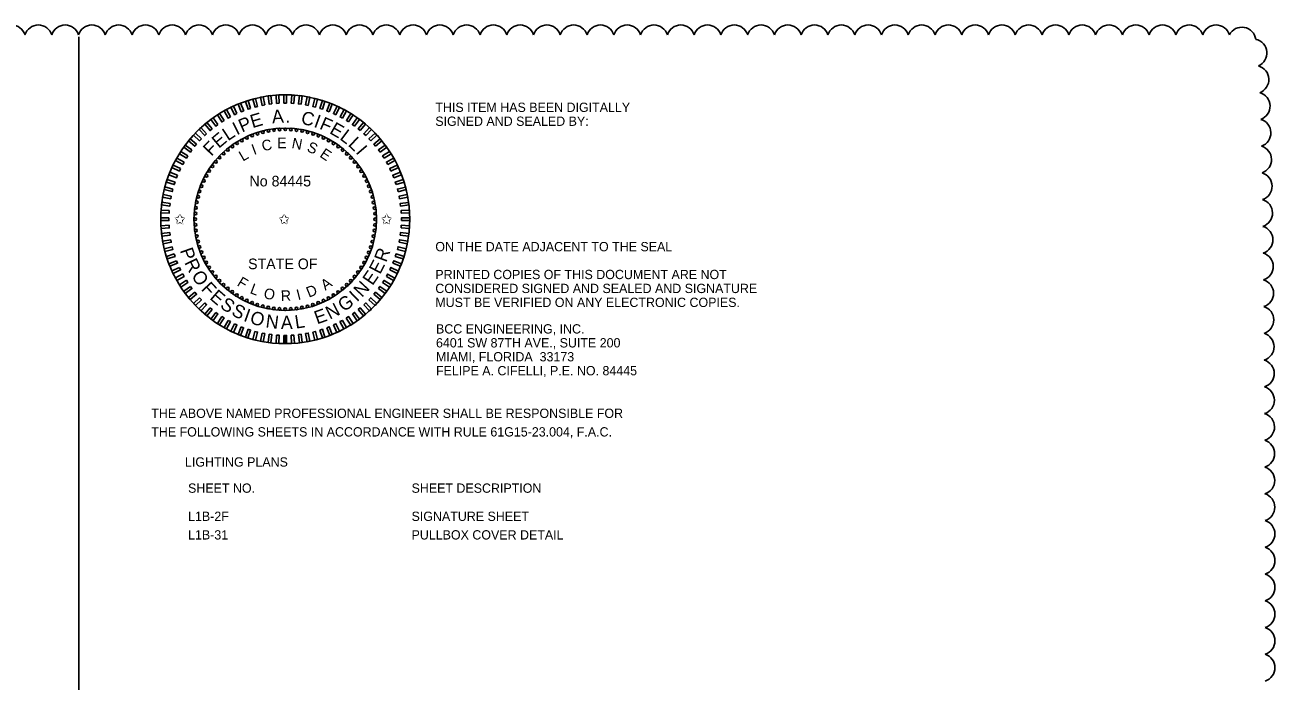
# Model space of a CAD drawing. Extents: x -811.2 to -767.6, y -2295.2 to -2235.1.
# Drawn here: x -777.02 to -767.6, y -2264.84 to -2259.9 of the extents above; entities that cross this region are included whole.
import ezdxf

# ---------------------------------------------------------------- set-up
doc = ezdxf.new("R2010")
doc.units = 0
for name, color, linetype in [('Cloud_dp', 7, 'Continuous'), ('PlotBorder_dp', 7, 'Continuous'), ('TextMinor', 7, 'Continuous'), ('TextMisc', 7, 'Continuous'), ('TextNotes', 7, 'Continuous'), ('TextShtNo', 7, 'Continuous')]:
    doc.layers.add(name, color=color, linetype=linetype)

msp = doc.modelspace()

# ---------------------------------------------------------------- linework, layer by layer
at = {"layer": 'Cloud_dp'}
for centre, radius, start, end in [((-777.1178, -2260.0023), 0.1057, 17.52079, 162.52079), ((-776.9163, -2260.0022), 0.1057, 17.51719, 162.51719), ((-776.7147, -2260.0022), 0.1057, 17.51375, 162.51375), ((-776.5132, -2260.0021), 0.1057, 17.51046, 162.51046), ((-776.3116, -2260.0021), 0.1057, 17.50731, 162.50731), ((-776.1101, -2260.0021), 0.1057, 17.50428, 162.50428), ((-775.9085, -2260.0021), 0.1057, 17.50138, 162.50138), ((-775.707, -2260.0021), 0.1057, 17.5, 162.5), ((-775.5054, -2260.0021), 0.1057, 17.5, 162.5), ((-775.3039, -2260.0021), 0.1057, 17.5, 162.5), ((-775.1023, -2260.0021), 0.1057, 17.5, 162.5), ((-774.9008, -2260.0021), 0.1057, 17.5, 162.5), ((-774.6992, -2260.0021), 0.1057, 17.5, 162.5), ((-774.4977, -2260.0021), 0.1057, 17.5, 162.5), ((-774.2961, -2260.0021), 0.1057, 17.5, 162.5), ((-774.0946, -2260.0021), 0.1057, 17.5, 162.5), ((-773.893, -2260.0021), 0.1057, 17.5, 162.5), ((-773.6915, -2260.0021), 0.1057, 17.5, 162.5), ((-773.4899, -2260.0021), 0.1057, 17.5, 162.5), ((-773.2884, -2260.0021), 0.1057, 17.5, 162.5), ((-773.0868, -2260.0021), 0.1057, 17.5, 162.5), ((-772.8853, -2260.0021), 0.1057, 17.5, 162.5), ((-772.6837, -2260.0021), 0.1057, 17.5, 162.5), ((-772.4822, -2260.0021), 0.1057, 17.5, 162.5), ((-772.2807, -2260.0021), 0.1057, 17.5, 162.5), ((-772.0791, -2260.0021), 0.1057, 17.5, 162.5), ((-771.8776, -2260.0021), 0.1057, 17.5, 162.5), ((-771.676, -2260.0021), 0.1057, 17.5, 162.5), ((-771.4745, -2260.0021), 0.1057, 17.5, 162.5), ((-771.2729, -2260.0021), 0.1057, 17.5, 162.5), ((-771.0714, -2260.0021), 0.1057, 17.5, 162.5), ((-770.8698, -2260.0021), 0.1057, 17.5, 162.5), ((-770.6683, -2260.0021), 0.1057, 17.5, 162.5), ((-770.4667, -2260.0021), 0.1057, 17.5, 162.5), ((-770.2652, -2260.0021), 0.1057, 17.5, 162.5), ((-770.0636, -2260.0021), 0.1057, 17.5, 162.5), ((-769.8621, -2260.0021), 0.1057, 17.5, 162.5), ((-769.6605, -2260.0021), 0.1057, 17.5, 162.5), ((-769.459, -2260.0021), 0.1057, 17.5, 162.5), ((-769.2574, -2260.0021), 0.1057, 17.5, 162.5), ((-769.0559, -2260.0021), 0.1057, 17.5, 162.5), ((-768.8543, -2260.0021), 0.1057, 17.5, 162.5), ((-768.6528, -2260.0021), 0.1057, 17.5, 162.5), ((-768.4512, -2260.0021), 0.1057, 17.5, 162.5), ((-768.2497, -2260.0021), 0.1057, 17.5, 162.5), ((-768.0481, -2260.0021), 0.1057, 17.5, 162.5), ((-767.8535, -2260.0187), 0.1056, 7.70605, 152.70605), ((-767.7706, -2260.108), 0.1057, 293.14506, 78.14506), ((-767.7558, -2260.3074), 0.1057, 290.35349, 75.35349), ((-767.7473, -2260.5083), 0.1057, 289.51862, 74.51862), ((-767.741, -2260.7095), 0.1057, 289.06556, 74.06556), ((-767.736, -2260.9109), 0.1057, 288.76987, 73.76987), ((-767.7319, -2261.1122), 0.1057, 288.55727, 73.55727), ((-767.7285, -2261.3137), 0.1057, 288.39488, 73.39488), ((-767.7255, -2261.5151), 0.1057, 288.2656, 73.2656), ((-767.723, -2261.7166), 0.1057, 288.1595, 73.1595), ((-767.7209, -2261.9181), 0.1057, 288.07039, 73.07039), ((-767.719, -2262.1196), 0.1057, 287.99417, 72.99417), ((-767.7174, -2262.3211), 0.1057, 287.928, 72.928), ((-767.716, -2262.5226), 0.1057, 287.86985, 72.86985), ((-767.7148, -2262.7241), 0.1057, 287.81821, 72.81821), ((-767.7137, -2262.9256), 0.1057, 287.77197, 72.77197), ((-767.7128, -2263.1272), 0.1057, 287.73023, 72.73023), ((-767.7121, -2263.3287), 0.1057, 287.69232, 72.69232), ((-767.7115, -2263.5302), 0.1057, 287.65767, 72.65767), ((-767.711, -2263.7318), 0.1057, 287.62586, 72.62586), ((-767.7106, -2263.9333), 0.1057, 287.5965, 72.5965), ((-767.7103, -2264.1348), 0.1057, 287.56931, 72.56931), ((-767.7101, -2264.3364), 0.1057, 287.54402, 72.54402), ((-767.71, -2264.5379), 0.1057, 287.52043, 72.52043), ((-767.71, -2264.7394), 0.1057, 287.50076, 72.50076)]:
    msp.add_arc(centre, radius, start, end, dxfattribs=at)
at = {"layer": 'TextMinor'}
for radius in [0.9375, 0.6875]:
    msp.add_circle((-775.0577, -2261.3603), radius, dxfattribs=at)
at = {"layer": 'TextNotes'}
msp.add_line((-776.6105, -2269.5845), (-776.6105, -2259.9845), dxfattribs=at)
at = {"layer": 'TextShtNo'}
for p, q in [((-775.0677, -2262.2978), (-775.0679, -2262.2353)), ((-775.0577, -2262.2978), (-775.0579, -2262.2353)), ((-775.0477, -2262.2978), (-775.0479, -2262.2353))]:
    msp.add_line(p, q, dxfattribs=at)
for points in [[(-775.3184, -2260.525), (-775.3376, -2260.5312), (-775.3569, -2260.4718), (-775.3377, -2260.4656)], [(-775.2654, -2260.5102), (-775.285, -2260.5152), (-775.3005, -2260.4548), (-775.281, -2260.4498)], [(-775.2117, -2260.4989), (-775.2315, -2260.5026), (-775.2432, -2260.4413), (-775.2234, -2260.4375)], [(-775.1573, -2260.4909), (-775.1773, -2260.4934), (-775.1851, -2260.4315), (-775.1651, -2260.4289)], [(-775.1025, -2260.4864), (-775.1226, -2260.4876), (-775.1265, -2260.4253), (-775.1064, -2260.424)], [(-775.0475, -2260.4853), (-775.0677, -2260.4853), (-775.0677, -2260.4228), (-775.0475, -2260.4228)], [(-774.9926, -2260.4876), (-775.0127, -2260.4864), (-775.0088, -2260.4241), (-774.9887, -2260.4253)], [(-774.9379, -2260.4934), (-774.9579, -2260.4909), (-774.9501, -2260.429), (-774.9301, -2260.4315)], [(-774.8837, -2260.5027), (-774.9036, -2260.4989), (-774.8919, -2260.4376), (-774.872, -2260.4413)], [(-774.8302, -2260.5153), (-774.8498, -2260.5103), (-774.8342, -2260.4498), (-774.8147, -2260.4548)], [(-774.7776, -2260.5312), (-774.7968, -2260.525), (-774.7775, -2260.4656), (-774.7583, -2260.4719)], [(-775.518, -2260.616), (-775.535, -2260.6268), (-775.5685, -2260.5741), (-775.5514, -2260.5633)], [(-775.4703, -2260.5886), (-775.488, -2260.5983), (-775.5181, -2260.5436), (-775.5004, -2260.5339)], [(-775.421, -2260.5642), (-775.4393, -2260.5728), (-775.4659, -2260.5163), (-775.4476, -2260.5077)], [(-775.3703, -2260.543), (-775.3891, -2260.5504), (-775.4121, -2260.4923), (-775.3933, -2260.4849)], [(-774.7261, -2260.5505), (-774.7449, -2260.543), (-774.7219, -2260.485), (-774.7031, -2260.4924)], [(-774.6759, -2260.5729), (-774.6942, -2260.5643), (-774.6676, -2260.5078), (-774.6493, -2260.5164)], [(-774.6272, -2260.5984), (-774.6449, -2260.5887), (-774.6148, -2260.534), (-774.5971, -2260.5437)], [(-774.5802, -2260.6269), (-774.5973, -2260.6161), (-774.5638, -2260.5634), (-774.5468, -2260.5742)], [(-775.6076, -2260.6796), (-775.6232, -2260.6925), (-775.663, -2260.6443), (-775.6474, -2260.6315)], [(-775.5638, -2260.6464), (-775.5801, -2260.6583), (-775.6168, -2260.6078), (-775.6005, -2260.5959)], [(-774.5351, -2260.6584), (-774.5515, -2260.6465), (-774.5148, -2260.596), (-774.4984, -2260.6079)], [(-774.4921, -2260.6926), (-774.5076, -2260.6797), (-774.4678, -2260.6316), (-774.4523, -2260.6445)], [(-775.7254, -2260.7947), (-775.7383, -2260.8102), (-775.7864, -2260.7704), (-775.7735, -2260.7549)], [(-775.6886, -2260.7539), (-775.7024, -2260.7686), (-775.7479, -2260.7258), (-775.7341, -2260.7111)], [(-775.6493, -2260.7155), (-775.664, -2260.7293), (-775.7067, -2260.6838), (-775.692, -2260.6699)], [(-774.4513, -2260.7294), (-774.466, -2260.7156), (-774.4232, -2260.6701), (-774.4085, -2260.6839)], [(-774.4128, -2260.7687), (-774.4267, -2260.754), (-774.3812, -2260.7113), (-774.3673, -2260.726)], [(-774.377, -2260.8104), (-774.3898, -2260.7948), (-774.3417, -2260.755), (-774.3289, -2260.7706)], [(-775.791, -2260.8828), (-775.8019, -2260.8999), (-775.8546, -2260.8664), (-775.8438, -2260.8494)], [(-775.7596, -2260.8377), (-775.7715, -2260.8541), (-775.822, -2260.8174), (-775.8101, -2260.801)], [(-774.3438, -2260.8542), (-774.3557, -2260.8379), (-774.3051, -2260.8012), (-774.2933, -2260.8175)], [(-774.3134, -2260.9), (-774.3242, -2260.883), (-774.2715, -2260.8495), (-774.2607, -2260.8666)], [(-775.8196, -2260.9298), (-775.8293, -2260.9475), (-775.884, -2260.9174), (-775.8743, -2260.8997)], [(-774.286, -2260.9477), (-774.2957, -2260.93), (-774.241, -2260.8999), (-774.2313, -2260.9176)], [(-775.8675, -2261.0287), (-775.875, -2261.0475), (-775.933, -2261.0245), (-775.9256, -2261.0057)], [(-775.8451, -2260.9785), (-775.8537, -2260.9968), (-775.9102, -2260.9702), (-775.9016, -2260.9519)], [(-774.2616, -2260.9969), (-774.2702, -2260.9787), (-774.2137, -2260.9521), (-774.2051, -2260.9704)], [(-774.2404, -2261.0477), (-774.2478, -2261.0289), (-774.1897, -2261.0059), (-774.1823, -2261.0247)], [(-775.9027, -2261.1328), (-775.9077, -2261.1524), (-775.9682, -2261.1368), (-775.9632, -2261.1173)], [(-775.8867, -2261.0802), (-775.893, -2261.0994), (-775.9524, -2261.0801), (-775.9461, -2261.0609)], [(-774.2223, -2261.0996), (-774.2286, -2261.0804), (-774.1692, -2261.0611), (-774.163, -2261.0803)], [(-774.2076, -2261.1526), (-774.2126, -2261.133), (-774.1522, -2261.1175), (-774.1471, -2261.137)], [(-775.9153, -2261.1863), (-775.9191, -2261.2062), (-775.9804, -2261.1945), (-775.9766, -2261.1746)], [(-774.1963, -2261.2063), (-774.2, -2261.1865), (-774.1387, -2261.1748), (-774.1349, -2261.1946)], [(-775.9304, -2261.2952), (-775.9316, -2261.3153), (-775.9939, -2261.3114), (-775.9927, -2261.2913)], [(-775.9245, -2261.2405), (-775.9271, -2261.2606), (-775.989, -2261.2527), (-775.9865, -2261.2327)], [(-774.1883, -2261.2607), (-774.1908, -2261.2407), (-774.1289, -2261.2329), (-774.1263, -2261.2529)], [(-774.1837, -2261.3155), (-774.185, -2261.2954), (-774.1227, -2261.2915), (-774.1214, -2261.3116)], [(-775.9327, -2261.3501), (-775.9327, -2261.3703), (-775.9952, -2261.3703), (-775.9952, -2261.3501)], [(-775.9316, -2261.4051), (-775.9304, -2261.4252), (-775.9927, -2261.4291), (-775.994, -2261.409)], [(-774.185, -2261.4254), (-774.1838, -2261.4053), (-774.1214, -2261.4092), (-774.1227, -2261.4293)], [(-774.1827, -2261.3705), (-774.1827, -2261.3503), (-774.1202, -2261.3503), (-774.1202, -2261.3705)], [(-775.9271, -2261.4599), (-775.9246, -2261.4799), (-775.9865, -2261.4877), (-775.989, -2261.4677)], [(-774.1908, -2261.4801), (-774.1883, -2261.4601), (-774.1264, -2261.4679), (-774.1289, -2261.4879)], [(-775.9191, -2261.5143), (-775.9153, -2261.5341), (-775.9767, -2261.5458), (-775.9805, -2261.526)], [(-775.9078, -2261.568), (-775.9027, -2261.5876), (-775.9632, -2261.6031), (-775.9682, -2261.5836)], [(-774.2127, -2261.5878), (-774.2077, -2261.5682), (-774.1472, -2261.5838), (-774.1522, -2261.6033)], [(-774.2001, -2261.5343), (-774.1963, -2261.5144), (-774.135, -2261.5261), (-774.1387, -2261.546)], [(-775.893, -2261.621), (-775.8868, -2261.6402), (-775.9462, -2261.6595), (-775.9524, -2261.6403)], [(-775.875, -2261.673), (-775.8676, -2261.6917), (-775.9256, -2261.7147), (-775.9331, -2261.6959)], [(-774.2479, -2261.6919), (-774.2404, -2261.6731), (-774.1824, -2261.6961), (-774.1898, -2261.7149)], [(-774.2286, -2261.6404), (-774.2224, -2261.6212), (-774.163, -2261.6405), (-774.1693, -2261.6597)], [(-775.8538, -2261.7237), (-775.8452, -2261.7419), (-775.9017, -2261.7685), (-775.9103, -2261.7502)], [(-775.8294, -2261.7729), (-775.8197, -2261.7906), (-775.8744, -2261.8207), (-775.8841, -2261.803)], [(-774.2958, -2261.7908), (-774.2861, -2261.7731), (-774.2314, -2261.8032), (-774.2411, -2261.8209)], [(-774.2703, -2261.7421), (-774.2617, -2261.7238), (-774.2052, -2261.7504), (-774.2138, -2261.7687)], [(-775.802, -2261.8206), (-775.7911, -2261.8376), (-775.8439, -2261.8711), (-775.8547, -2261.854)], [(-775.7716, -2261.8664), (-775.7597, -2261.8827), (-775.8102, -2261.9194), (-775.8221, -2261.9031)], [(-774.3558, -2261.8829), (-774.3439, -2261.8665), (-774.2934, -2261.9032), (-774.3052, -2261.9196)], [(-774.3243, -2261.8378), (-774.3135, -2261.8207), (-774.2608, -2261.8542), (-774.2716, -2261.8712)], [(-775.7384, -2261.9102), (-775.7255, -2261.9258), (-775.7737, -2261.9656), (-775.7865, -2261.95)], [(-775.7025, -2261.9519), (-775.6887, -2261.9666), (-775.7342, -2262.0093), (-775.7481, -2261.9946)], [(-774.4268, -2261.9667), (-774.413, -2261.952), (-774.3675, -2261.9948), (-774.3813, -2262.0095)], [(-774.39, -2261.9259), (-774.3771, -2261.9104), (-774.329, -2261.9502), (-774.3419, -2261.9657)], [(-775.6641, -2261.9912), (-775.6494, -2262.005), (-775.6921, -2262.0505), (-775.7069, -2262.0367)], [(-775.6233, -2262.028), (-775.6078, -2262.0409), (-775.6476, -2262.089), (-775.6631, -2262.0761)], [(-775.5803, -2262.0622), (-775.5639, -2262.0741), (-775.6006, -2262.1246), (-775.617, -2262.1127)], [(-774.5516, -2262.0742), (-774.5353, -2262.0623), (-774.4986, -2262.1129), (-774.5149, -2262.1247)], [(-774.5078, -2262.041), (-774.4922, -2262.0281), (-774.4524, -2262.0763), (-774.468, -2262.0891)], [(-774.4661, -2262.0051), (-774.4514, -2261.9913), (-774.4087, -2262.0368), (-774.4234, -2262.0507)], [(-775.5352, -2262.0937), (-775.5181, -2262.1045), (-775.5516, -2262.1572), (-775.5686, -2262.1464)], [(-775.4882, -2262.1222), (-775.4705, -2262.1319), (-775.5006, -2262.1866), (-775.5182, -2262.1769)], [(-775.4395, -2262.1477), (-775.4212, -2262.1563), (-775.4478, -2262.2128), (-775.4661, -2262.2042)], [(-774.6943, -2262.1564), (-774.6761, -2262.1478), (-774.6495, -2262.2043), (-774.6678, -2262.2129)], [(-774.6451, -2262.132), (-774.6274, -2262.1223), (-774.5973, -2262.177), (-774.615, -2262.1867)], [(-774.5974, -2262.1046), (-774.5804, -2262.0938), (-774.5469, -2262.1465), (-774.564, -2262.1573)], [(-775.3893, -2262.1701), (-775.3705, -2262.1776), (-775.3935, -2262.2356), (-775.4123, -2262.2282)], [(-775.3378, -2262.1894), (-775.3186, -2262.1956), (-775.3379, -2262.255), (-775.3571, -2262.2487)], [(-775.2852, -2262.2053), (-775.2656, -2262.2103), (-775.2811, -2262.2708), (-775.3007, -2262.2658)], [(-775.2317, -2262.2179), (-775.2118, -2262.2217), (-775.2235, -2262.283), (-775.2434, -2262.2793)], [(-775.1775, -2262.2272), (-775.1574, -2262.2297), (-775.1653, -2262.2916), (-775.1853, -2262.2891)], [(-775.1228, -2262.233), (-775.1027, -2262.2342), (-775.1066, -2262.2966), (-775.1267, -2262.2953)], [(-775.0679, -2262.2353), (-775.0477, -2262.2353), (-775.0477, -2262.2978), (-775.0679, -2262.2978)], [(-775.0129, -2262.2342), (-774.9928, -2262.233), (-774.9888, -2262.2953), (-775.009, -2262.2966)], [(-774.9581, -2262.2297), (-774.9381, -2262.2272), (-774.9303, -2262.2891), (-774.9503, -2262.2917)], [(-774.9037, -2262.2217), (-774.8839, -2262.218), (-774.8722, -2262.2793), (-774.892, -2262.2831)], [(-774.8499, -2262.2104), (-774.8304, -2262.2054), (-774.8149, -2262.2658), (-774.8344, -2262.2709)], [(-774.797, -2262.1957), (-774.7778, -2262.1894), (-774.7585, -2262.2488), (-774.7777, -2262.255)], [(-774.745, -2262.1776), (-774.7263, -2262.1702), (-774.7033, -2262.2283), (-774.7221, -2262.2357)]]:
    msp.add_lwpolyline(points, close=True, dxfattribs=at)
for centre in [(-775.3836, -2260.7664), (-775.3456, -2260.7471), (-775.3066, -2260.7302), (-775.2665, -2260.7158), (-775.2256, -2260.704), (-775.1841, -2260.6947), (-775.142, -2260.6881), (-775.0997, -2260.6841), (-775.0571, -2260.6828), (-775.0146, -2260.6842), (-774.9722, -2260.6882), (-774.9302, -2260.6949), (-774.8887, -2260.7043), (-774.8478, -2260.7162), (-774.8078, -2260.7306), (-774.7687, -2260.7476), (-775.4891, -2260.8379), (-775.4554, -2260.8119), (-775.4202, -2260.788), (-774.7308, -2260.7669), (-774.6942, -2260.7886), (-774.659, -2260.8125), (-774.6254, -2260.8387), (-775.5793, -2260.928), (-775.5512, -2260.8961), (-775.521, -2260.8661), (-774.5935, -2260.8668), (-774.5635, -2260.897), (-774.5353, -2260.9289), (-775.6511, -2261.0334), (-775.6294, -2260.9968), (-775.6054, -2260.9616), (-774.5093, -2260.9626), (-774.4854, -2260.9978), (-774.4638, -2261.0344), (-775.6874, -2261.1104), (-775.6704, -2261.0713), (-774.4445, -2261.0724), (-774.4276, -2261.1114), (-775.7231, -2261.2328), (-775.7137, -2261.1913), (-775.7018, -2261.1504), (-774.4132, -2261.1515), (-774.4014, -2261.1924), (-774.3921, -2261.2339), (-775.7338, -2261.3172), (-775.7297, -2261.2748), (-774.3855, -2261.276), (-774.3815, -2261.3183), (-775.7352, -2261.3597), (-775.7339, -2261.4023), (-774.3816, -2261.4034), (-774.3802, -2261.3609), (-775.7299, -2261.4447), (-775.7233, -2261.4867), (-774.3923, -2261.4878), (-774.3856, -2261.4458), (-775.714, -2261.5282), (-775.7022, -2261.5691), (-775.6878, -2261.6092), (-774.428, -2261.6102), (-774.4136, -2261.5702), (-774.4016, -2261.5293), (-775.6709, -2261.6482), (-775.6516, -2261.6862), (-774.4643, -2261.6872), (-774.4449, -2261.6493), (-775.63, -2261.7228), (-775.6061, -2261.7581), (-775.58, -2261.7917), (-774.5361, -2261.7926), (-774.5099, -2261.759), (-774.486, -2261.7238), (-775.5519, -2261.8236), (-775.5219, -2261.8538), (-775.49, -2261.8819), (-774.6263, -2261.8827), (-774.5943, -2261.8545), (-774.5642, -2261.8245), (-775.4564, -2261.9081), (-775.4212, -2261.932), (-775.3846, -2261.9537), (-775.3467, -2261.9731), (-775.3076, -2261.99), (-774.7698, -2261.9735), (-774.7318, -2261.9542), (-774.6952, -2261.9326), (-774.6599, -2261.9087), (-775.2676, -2262.0044), (-775.2267, -2262.0163), (-775.1852, -2262.0257), (-775.1432, -2262.0324), (-775.1008, -2262.0364), (-775.0577, -2262.0378), (-775.0157, -2262.0365), (-774.9733, -2262.0325), (-774.9313, -2262.0259), (-774.8898, -2262.0166), (-774.8489, -2262.0048), (-774.8088, -2261.9904)]:
    msp.add_circle(centre, 0.01, dxfattribs=at)

# ---------------------------------------------------------------- texts
at = {"layer": 'PlotBorder_dp'}
for s, p in [('THIS ITEM HAS BEEN DIGITALLY', (-773.9272, -2260.5516)), ('SIGNED AND SEALED BY:', (-773.9272, -2260.6566)), ('ON THE DATE ADJACENT TO THE SEAL', (-773.9272, -2261.6016)), ('PRINTED COPIES OF THIS DOCUMENT ARE NOT ', (-773.9272, -2261.8116)), ('CONSIDERED SIGNED AND SEALED AND SIGNATURE ', (-773.9272, -2261.9166)), ('MUST BE VERIFIED ON ANY ELECTRONIC COPIES.', (-773.9272, -2262.0216)), ('BCC ENGINEERING, INC.', (-773.9222, -2262.2215)), ('6401 SW 87TH AVE., SUITE 200', (-773.9222, -2262.3265)), ('MIAMI, FLORIDA  33173', (-773.9222, -2262.4315)), ('FELIPE A. CIFELLI, P.E. NO. 84445', (-773.9222, -2262.5365)), ('THE ABOVE NAMED PROFESSIONAL ENGINEER SHALL BE RESPONSIBLE FOR ', (-776.0663, -2262.8576)), ('THE FOLLOWING SHEETS IN ACCORDANCE WITH RULE 61G15-23.004, F.A.C.', (-776.0663, -2262.9976)), ('LIGHTING PLANS', (-775.8125, -2263.2246))]:
    msp.add_text(s, height=0.07, dxfattribs=at).set_placement(p)
at = {"layer": 'TextMisc'}
for s, p in [('SHEET NO.', (-775.7891, -2263.4216)), ('SHEET DESCRIPTION', (-774.1062, -2263.4216)), ('L1B-2F', (-775.7891, -2263.6338)), ('SIGNATURE SHEET', (-774.1062, -2263.6338)), ('L1B-31', (-775.7891, -2263.7738)), ('PULLBOX COVER DETAIL', (-774.1062, -2263.7738))]:
    msp.add_text(s, height=0.07, dxfattribs=at).set_placement(p)
at = {"layer": 'TextShtNo'}
for s, height, rotation, p in [('E', 0.1, 16.54261, (-775.3041, -2260.6746)), ('A', 0.1, 4.42103, (-775.1546, -2260.6381)), ('C', 0.1, 347.7999, (-774.944, -2260.6406)), ('I', 0.1, 26.81606, (-775.4224, -2260.7295)), ('P', 0.1, 23.28287, (-775.3829, -2260.7082)), ('.', 0.1, 356.65403, (-775.0561, -2260.6317)), ('I', 0.1, 340.0631, (-774.8481, -2260.6624)), ('F', 0.1, 336.52991, (-774.8055, -2260.6767)), ('E', 0.1, 330.07956, (-774.7303, -2260.7093)), ('E', 0.1, 40.12142, (-775.5578, -2260.8304)), ('L', 0.1, 33.07918, (-775.4891, -2260.7731)), ('E', 0.08, 0.41861, (-775.1174, -2260.8252)), ('N', 0.08, 349.29143, (-775.013, -2260.8238)), ('L', 0.1, 323.03732, (-774.653, -2260.7544)), ('L', 0.1, 316.7742, (-774.5893, -2260.8022)), ('F', 0.1, 46.57177, (-775.6142, -2260.8899)), ('L', 0.08, 30.40215, (-775.3768, -2260.9267)), ('I', 0.08, 20.01168, (-775.2934, -2260.8762)), ('C', 0.08, 12.20255, (-775.2254, -2260.8487)), ('S', 0.08, 337.02207, (-774.9, -2260.8455)), ('E', 0.08, 325.86633, (-774.8034, -2260.8857)), ('I', 0.1, 310.51108, (-774.5312, -2260.8566)), ('P', 0.1, 289.40551, (-775.8524, -2261.5949)), ('R', 0.1, 69.5134, (-774.2975, -2261.69)), ('R', 0.1, 296.14576, (-775.8194, -2261.6865)), ('E', 0.1, 62.47116, (-774.3437, -2261.7807)), ('O', 0.1, 303.96711, (-775.7679, -2261.7872)), ('E', 0.1, 55.42892, (-774.4006, -2261.8651)), ('F', 0.1, 312.62798, (-775.6955, -2261.8892)), ('F', 0.08, 328.72408, (-775.4257, -2261.8569)), ('L', 0.08, 339.29159, (-775.3284, -2261.916)), ('O', 0.08, 349.68206, (-775.2238, -2261.9557)), ('D', 0.08, 22.01279, (-774.8796, -2261.9522)), ('A', 0.08, 34.49917, (-774.7559, -2261.8997)), ('N', 0.1, 47.17876, (-774.4798, -2261.9542)), ('E', 0.1, 319.07833, (-775.6321, -2261.9575)), ('S', 0.1, 326.12056, (-775.5545, -2262.0234)), ('R', 0.08, 2.33977, (-775.0893, -2261.9776)), ('I', 0.08, 14.20366, (-774.9617, -2261.9709)), ('G', 0.1, 35.11153, (-774.6167, -2262.0618)), ('I', 0.1, 43.64556, (-774.5175, -2261.9886)), ('S', 0.1, 333.193, (-775.4691, -2262.0796)), ('I', 0.1, 340.26543, (-775.3774, -2262.1248)), ('O', 0.1, 343.79863, (-775.3297, -2262.143)), ('E', 0.1, 19.81912, (-774.8174, -2262.1533)), ('N', 0.1, 26.86136, (-774.722, -2262.1179)), ('N', 0.1, 352.45949, (-775.2087, -2262.175)), ('A', 0.1, 0.70966, (-775.0902, -2262.1883)), ('L', 0.1, 8.47665, (-774.978, -2262.1851))]:
    msp.add_text(s, height=height, rotation=rotation, dxfattribs=at).set_placement(p)
for s, p in [('No 84445', (-775.3267, -2261.1131)), ('✩', (-775.8927, -2261.3983)), ('✩', (-775.108, -2261.3983)), ('✩', (-774.3361, -2261.3983)), ('STATE OF', (-775.3374, -2261.7365))]:
    msp.add_text(s, height=0.08, dxfattribs=at).set_placement(p)

doc.saveas('drawing.dxf')
